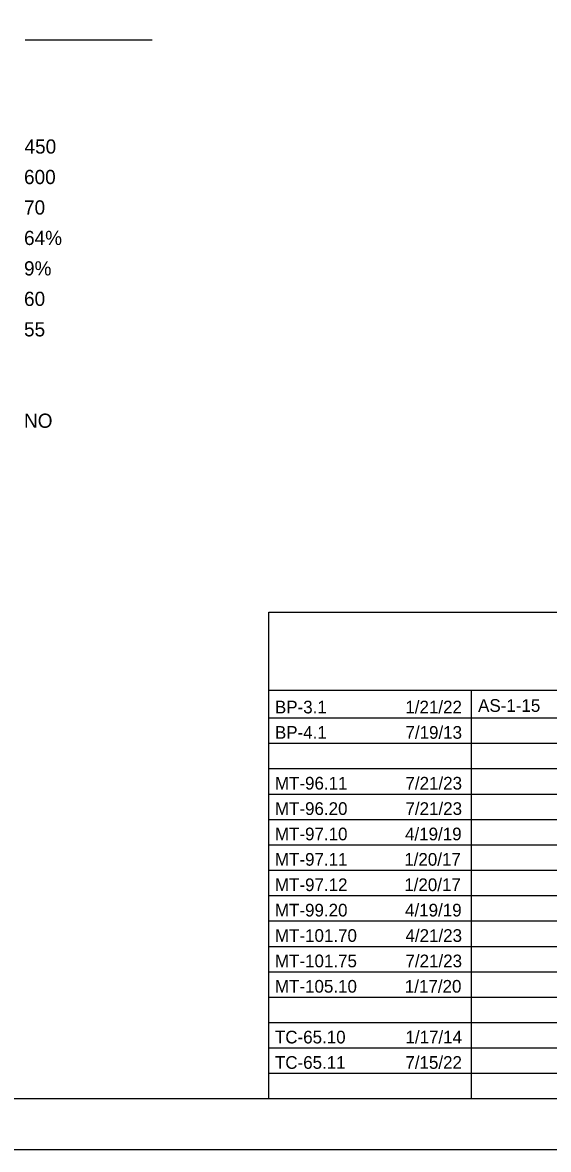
# Model space of a CAD drawing. Extents: x 0 to 34, y 0 to 22.
# Drawn here: x 7.72 to 12.91, y 0 to 11.1 of the extents above; entities that cross this region are included whole.
import ezdxf

# ---------------------------------------------------------------- set-up
doc = ezdxf.new("R2010")
doc.units = 0
for name, color, linetype in [('Default', 7, 'Continuous'), ('SH_Border', 7, 'Continuous'), ('SH_Cut_Line', 7, 'Continuous'), ('SH_Data', 7, 'Continuous'), ('SH_Text', 7, 'Continuous')]:
    doc.layers.add(name, color=color, linetype=linetype)

msp = doc.modelspace()

# ---------------------------------------------------------------- linework, layer by layer
at = {"layer": 'SH_Border'}
msp.add_lwpolyline([(1.5, 21.5), (33.5, 21.5), (33.5, 0.5), (1.5, 0.5)], close=True, dxfattribs=at)
at = {"layer": 'SH_Cut_Line'}
msp.add_lwpolyline([(0, 0), (34, 0), (34, 22), (0, 22)], close=True, dxfattribs=at)
at = {"layer": 'SH_Data'}
for p, q in [((9, 10.922), (7.75, 10.922)), ((10.15, 5.292), (23.6, 5.292)), ((10.15, 0.5), (10.15, 5.292)), ((10.15, 4.521), (23.6, 4.521)), ((12.15, 0.5), (12.15, 4.521)), ((10.15, 4.25), (23.6, 4.25)), ((10.15, 4), (23.6, 4)), ((10.15, 3.75), (23.6, 3.75)), ((10.15, 3.5), (23.6, 3.5)), ((10.15, 3.25), (23.6, 3.25)), ((10.15, 3), (23.6, 3)), ((10.15, 2.75), (23.6, 2.75)), ((10.15, 2.5), (23.6, 2.5)), ((10.15, 2.25), (23.6, 2.25)), ((10.15, 2), (23.6, 2)), ((10.15, 1.75), (23.6, 1.75)), ((10.15, 1.5), (23.6, 1.5)), ((10.15, 1.25), (23.6, 1.25)), ((10.15, 1), (23.6, 1)), ((10.15, 0.75), (23.6, 0.75))]:
    msp.add_line(p, q, dxfattribs=at)

# ---------------------------------------------------------------- texts
at = {"layer": 'Default'}
for s, p in [('BP-3.1', (10.211, 4.294)), ('1/21/22', (11.497, 4.294)), ('AS-1-15', (12.214, 4.309)), ('BP-4.1', (10.211, 4.044)), ('7/19/13', (11.498, 4.044)), ('MT-96.11', (10.211, 3.544)), ('7/21/23', (11.498, 3.544)), ('MT-96.20', (10.211, 3.294)), ('7/21/23', (11.498, 3.294)), ('MT-97.10', (10.211, 3.044)), ('4/19/19', (11.494, 3.044)), ('MT-97.11', (10.211, 2.794)), ('1/20/17', (11.486, 2.794)), ('MT-97.12', (10.211, 2.544)), ('1/20/17', (11.486, 2.544)), ('MT-99.20', (10.211, 2.294)), ('4/19/19', (11.494, 2.294)), ('MT-101.70', (10.211, 2.044)), ('4/21/23', (11.498, 2.044)), ('MT-101.75', (10.211, 1.794)), ('7/21/23', (11.498, 1.794)), ('MT-105.10', (10.211, 1.544)), ('1/17/20', (11.492, 1.544)), ('TC-65.10', (10.211, 1.044)), ('1/17/14', (11.498, 1.044)), ('TC-65.11', (10.211, 0.794)), ('7/15/22', (11.497, 0.794))]:
    msp.add_text(s, height=0.125, dxfattribs=at).set_placement(p)
at = {"layer": 'SH_Text'}
for s, p in [('450', (7.742, 9.806)), ('600', (7.737, 9.506)), ('70', (7.737, 9.206)), ('64%', (7.737, 8.906)), ('9%', (7.737, 8.606)), ('60', (7.737, 8.306)), ('55', (7.737, 8.006)), ('NO', (7.737, 7.106))]:
    msp.add_text(s, height=0.14, dxfattribs=at).set_placement(p)

doc.saveas('drawing.dxf')
